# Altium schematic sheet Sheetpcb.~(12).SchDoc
size A; SheetNumber: 1; SheetTotal: 1
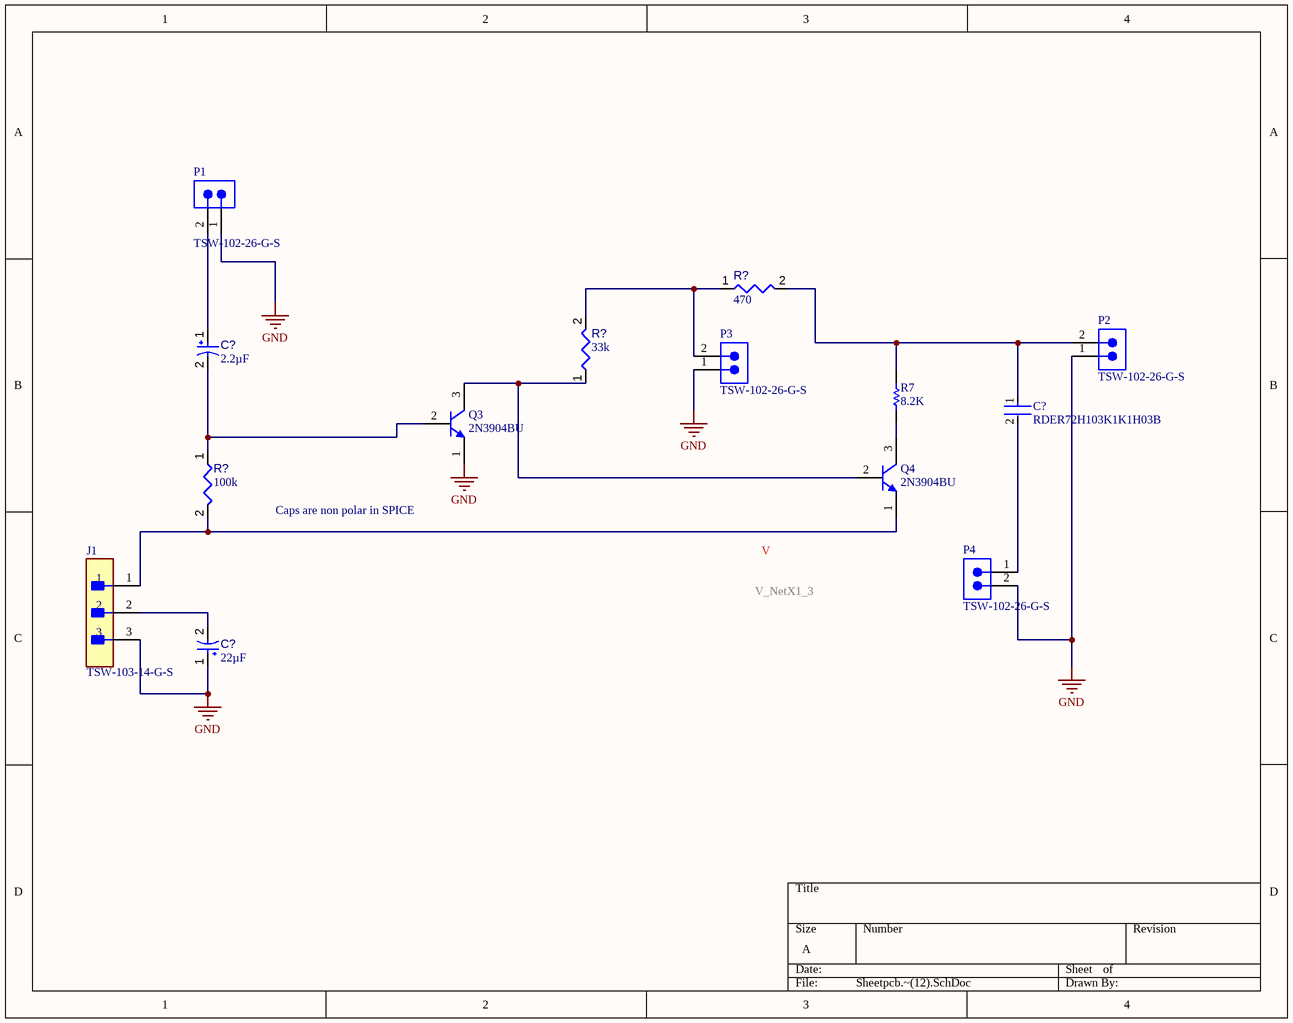
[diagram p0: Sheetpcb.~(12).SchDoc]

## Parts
(Parts that share a designator on the sheet are numbered #1, #2 ... from top to bottom, then left to right.)
C?#1  value 2.2µF  [CAPPR55-200-1100X500X1200]  (hidden comment: ECA1HM2R2)
C?#2  RDER72H103K1K1H03B  [FP-RDE1K1-MFG]
C?#3  value 22µF  [CAPPR55-200-1100X500X1200]  (hidden comment: ECA1HM220)
J1  TSW-103-14-G-S  [FP-TSW-103-14-G-S-MFG]
P1  TSW-102-26-G-S  [SMTC-TSW-102-26-XX-S]
P2  TSW-102-26-G-S  [SMTC-TSW-102-26-XX-S]
P3  TSW-102-26-G-S  [SMTC-TSW-102-26-XX-S]
P4  TSW-102-26-G-S  [SMTC-TSW-102-26-XX-S]
Q3  2N3904BU  [FAIR-TO-92]
Q4  2N3904BU  [FAIR-TO-92]
R7  value 8.2K  (hidden comment: Resistor)
R?#1  value 470  [RESC0805(2012)_L]  (hidden comment: Resistor 470R +/-5% 0805 125 mW)
R?#2  value 33k  [Resistor 33K ohm]  (hidden comment: 33K Ohm Generic Through Hole Resistor)
R?#3  value 100k  [RESA60-630X240]  (hidden comment: MFR-25FBF52-100K)

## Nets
GND: C?#3.1 J1.3 P1.1 P2.1 P3.1 P4.2 Q3.1(E)
NetC?#1_1: C?#1.1 P1.2
NetC?#1_2: C?#1.2 Q3.2(B) R?#3.1
NetC?#2_1: C?#2.1 P2.2 R7.1 R?#1.2
NetC?#2_2: C?#2.2 P4.1
NetC?#3_2: C?#3.2 J1.2
NetJ1_1: J1.1 Q4.1(E) R?#3.2
NetP3_2: P3.2 R?#1.1 R?#2.2
NetQ3_3: Q3.3(C) Q4.2(B) R?#2.1
NetQ4_3: Q4.3(C) R7.2

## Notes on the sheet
- Caps are non polar in SPICE

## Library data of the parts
C?#1 = CMP-001-00029-7: Aluminum Electrolytic Capacitor, 2.2 uF, +/- 20%, 50 V, -40 to 85 degC, 2-Pin THD, RoHS, Bulk; Manufacturer: Panasonic; Voltage Rating: 50V; Ripple Current: 20mA
C?#2 = CMP-06035-024341-1: Ceramic Capacitor 10nF ±10% 500V X7R Radial
C?#3 = CMP-001-00027-7: Aluminum Electrolytic Capacitor, 22 uF, +/- 20%, 50 V, -40 to 85 degC, 2-Pin THD, RoHS, Bulk; Manufacturer: Panasonic; Ripple Current (AC): 100mA; Voltage Rating: 50V
J1 = CMP-02766-001743-1: CONN HEADER VERT 3POS 2.54MM; Max Voltage Rating (AC): 550V; Number of Positions: 3; Max Current Rating: 7.6A; Gender: Male
P1-P4 = CMP-1024-00327-1: 0.025" SQ Post Header, Through-hole, Vertical, -55 to 125 degC, 2.54 mm Pitch, 2-Pin, Male, RoHS; Manufacturer: Samtec; Pitch: 2.54 mm
Q3 Q4 = CMP-2000-04944-1: NPN General-Purpose Amplifier, 40 V VCEO, 0.2 A, -55 to 150 degC, 2-Pin TO-92, RoHS, Bulk; Manufacturer: FairchildSemiconductor; Maximum Collector Base Voltage: 60V; Minimum DC Current Gain: 40@0.1mA@1V; Maximum Collector Emitter Voltage: 40V; Maximum DC Collector Current: 0.2A; Rad Hard: No; Maximum Operating Frequency: 300(Min)MHz; Maximum Collector Emitter Saturation Voltage: 0.2@1mA@10mA; Maximum Power Dissipation: 625mW
R7 = Resistor: TC1: 0; SimulationGenericComponent: True
R?#1 = CMP-009-00122-3: Chip Resistor, 470 Ohms, +/-5%, 125 mW, -55 to 155 degC, 0805; Tolerance: 5%; Power: 125mW
R?#2 = CMP-009-00177-1: Power: 250mW
R?#3 = CMP-009-00045-4: Axial Resistor, 100 KOhm, +/- 1%, 0.25 W, -55 to 155 degC, 2-Pin THD, RoHS, Bulk; Manufacturer: Yageo; Power: 250mW; Voltage Rating: 250V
